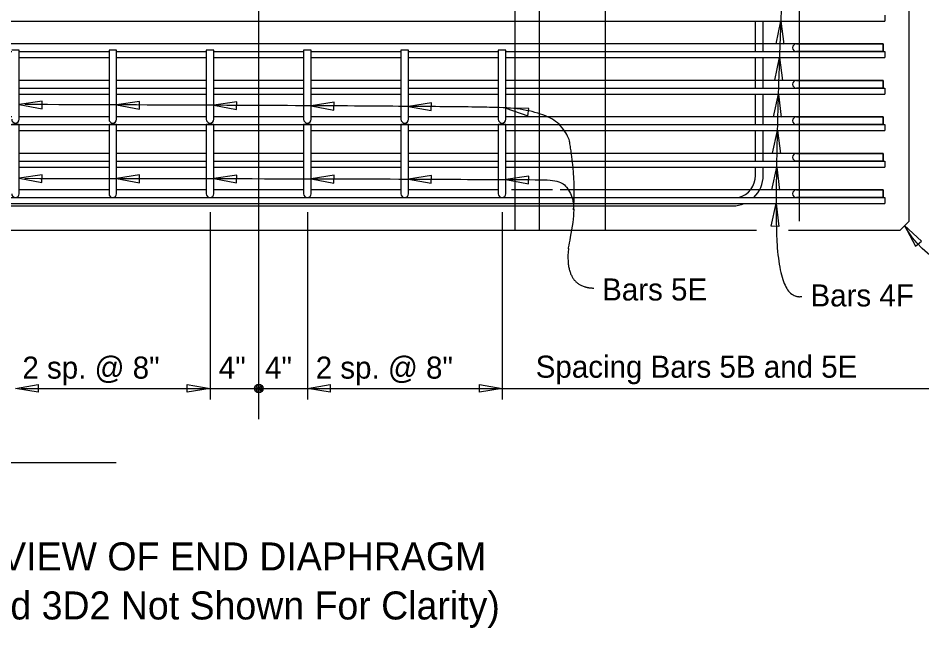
# Model space of a CAD drawing. Extents: x 120658.6 to 120712.1, y 120647.1 to 120669.9.
# Drawn here: x 120663.4 to 120669.6, y 120649.38 to 120653.56 of the extents above; entities that cross this region are included whole.
import ezdxf

# ---------------------------------------------------------------- set-up
doc = ezdxf.new("R2010")
doc.units = 0
for name, color, linetype in [('BeamConc', 7, 'Continuous'), ('BeamConc_h', 7, 'Continuous'), ('CL_Major', 7, 'Continuous'), ('Dimension', 7, 'Continuous'), ('Miscellaneous', 7, 'Continuous'), ('Rebar', 7, 'Continuous'), ('Rebar_h', 7, 'Continuous'), ('TextStructures', 7, 'Continuous')]:
    doc.layers.add(name, color=color, linetype=linetype)

msp = doc.modelspace()

# ---------------------------------------------------------------- linework, layer by layer
at = {"layer": 'BeamConc'}
for p, q in [((120669.5083, 120652.1656), (120669.5083, 120656.3833)), ((120669.4458, 120652.1031), (120669.5083, 120652.1656)), ((120660.7375, 120652.1031), (120668.4636, 120652.1031)), ((120668.6828, 120652.1031), (120669.4458, 120652.1031))]:
    msp.add_line(p, q, dxfattribs=at)
at = {"layer": 'BeamConc_h'}
for p, q in [((120667.425, 120656.3833), (120667.425, 120652.1031)), ((120668.7583, 120652.1656), (120668.7583, 120656.3833))]:
    msp.add_line(p, q, dxfattribs=at)
at = {"layer": 'CL_Major'}
msp.add_line((120665.0529, 120650.8078), (120665.0529, 120655.6993), dxfattribs=at)
at = {"layer": 'Dimension'}
for p, q in [((120664.7196, 120652.2276), (120664.7196, 120650.9437)), ((120665.3862, 120652.2276), (120665.3862, 120650.9437)), ((120666.7196, 120652.2276), (120666.7196, 120650.9437)), ((120663.425, 120651.0193), (120669.8858, 120651.0193)), ((120664.0762, 120650.5097), (120659.6749, 120650.5097))]:
    msp.add_line(p, q, dxfattribs=at)
for points in [[(120668.6295, 120653.5354), (120668.6493, 120653.3782), (120668.5964, 120653.3805)], [(120668.6206, 120653.2854), (120668.6403, 120653.1282), (120668.5874, 120653.1305)], [(120668.6128, 120653.0354), (120668.6325, 120652.8782), (120668.5797, 120652.8805)], [(120663.4122, 120652.9636), (120663.568, 120652.9349), (120663.5688, 120652.9878)], [(120664.0789, 120652.9614), (120664.2347, 120652.9326), (120664.2355, 120652.9855)], [(120664.7456, 120652.9586), (120664.9014, 120652.9299), (120664.9021, 120652.9828)], [(120665.4122, 120652.9553), (120665.568, 120652.9265), (120665.5688, 120652.9794)], [(120666.0789, 120652.9508), (120666.2347, 120652.922), (120666.2355, 120652.9749)], [(120666.7456, 120652.9381), (120666.8951, 120652.8857), (120666.904, 120652.9379)], [(120668.6063, 120652.7854), (120668.626, 120652.6282), (120668.5731, 120652.6305)], [(120668.6009, 120652.5354), (120668.6206, 120652.3782), (120668.5677, 120652.3805)], [(120663.4117, 120652.4584), (120663.5674, 120652.4297), (120663.5682, 120652.4826)], [(120664.0789, 120652.4575), (120664.2347, 120652.4287), (120664.2355, 120652.4816)], [(120664.7456, 120652.4564), (120664.9014, 120652.4276), (120664.9021, 120652.4805)], [(120665.4122, 120652.455), (120665.568, 120652.4262), (120665.5688, 120652.4791)], [(120666.0789, 120652.4531), (120666.2347, 120652.4243), (120666.2355, 120652.4772)], [(120666.7456, 120652.4495), (120666.9014, 120652.4207), (120666.9021, 120652.4736)], [(120668.5969, 120652.2854), (120668.6166, 120652.1282), (120668.5637, 120652.1305)], [(120669.4771, 120652.1344), (120669.5517, 120651.9946), (120669.5936, 120652.027)], [(120663.3862, 120651.0193), (120663.5419, 120651.0459), (120663.5419, 120650.9926)], [(120664.7195, 120651.0193), (120664.5633, 120650.9928), (120664.5633, 120651.0457)], [(120665.3862, 120651.0193), (120665.5424, 120651.0457), (120665.5424, 120650.9928)], [(120666.7195, 120651.0193), (120666.5639, 120650.9926), (120666.5639, 120651.0459)]]:
    msp.add_lwpolyline(points, close=True, dxfattribs=at)
for radius in [0.0299, 0.0196, 0.00888]:
    msp.add_circle((120665.0526, 120651.0188), radius, dxfattribs=at)
for points, degree in [([(120668.6397, 120653.7854), (120668.5921, 120652.6793), (120668.6046, 120651.6182), (120668.7732, 120651.6494)], 2), ([(120667.2092, 120652.2424), (120667.2258, 120652.4514), (120667.1449, 120652.9323), (120666.2289, 120652.9547), (120663.451, 120652.9637)], 2), ([(120663.4505, 120652.4585), (120666.8193, 120652.4545), (120667.2662, 120652.4382), (120667.1133, 120651.7115), (120667.3478, 120651.7067)], 2), ([(120670.6709, 120651.1441), (120670.3358, 120651.1038), (120670.1648, 120651.7005), (120669.6069, 120651.8964), (120669.4771, 120652.1344)], 3)]:
    msp.add_open_spline(points, degree=degree, dxfattribs=at)
at = {"layer": 'Miscellaneous'}
for p, q in [((120666.8065, 120654.1031), (120666.8065, 120652.1031)), ((120666.9732, 120654.1031), (120666.9732, 120652.1031))]:
    msp.add_line(p, q, dxfattribs=at)
at = {"layer": 'Rebar'}
for p, q in [((120669.3417, 120653.5771), (120669.3417, 120653.5354)), ((120660.8417, 120653.5354), (120669.3417, 120653.5354)), ((120668.4563, 120653.3271), (120668.4563, 120653.5354)), ((120668.5083, 120653.3271), (120668.5083, 120653.5354)), ((120668.7363, 120653.3792), (120669.3303, 120653.3792)), ((120669.3303, 120653.3792), (120669.3303, 120653.3271)), ((120663.4122, 120653.3371), (120663.3602, 120653.3371)), ((120663.4122, 120652.8631), (120663.4122, 120653.3371)), ((120663.4122, 120653.3271), (120664.0268, 120653.3271)), ((120664.0268, 120653.3371), (120664.0268, 120652.8631)), ((120664.0789, 120653.3371), (120664.0268, 120653.3371)), ((120664.0789, 120652.8631), (120664.0789, 120653.3371)), ((120664.0789, 120653.3271), (120664.6935, 120653.3271)), ((120664.6935, 120653.3371), (120664.6935, 120652.8631)), ((120664.7456, 120653.3371), (120664.6935, 120653.3371)), ((120664.7456, 120652.8631), (120664.7456, 120653.3371)), ((120664.7456, 120653.3271), (120665.3602, 120653.3271)), ((120665.3602, 120653.3371), (120665.3602, 120652.8631)), ((120665.4122, 120653.3371), (120665.3602, 120653.3371)), ((120665.4122, 120652.8631), (120665.4122, 120653.3371)), ((120665.4122, 120653.3271), (120666.0268, 120653.3271)), ((120666.0268, 120653.3371), (120666.0268, 120652.8631)), ((120666.0789, 120653.3371), (120666.0268, 120653.3371)), ((120666.0789, 120652.8631), (120666.0789, 120653.3371)), ((120666.0789, 120653.3271), (120666.6935, 120653.3271)), ((120666.6935, 120653.3371), (120666.6935, 120652.8631)), ((120666.7456, 120653.3371), (120666.6935, 120653.3371)), ((120666.7456, 120652.8631), (120666.7456, 120653.3371)), ((120666.7456, 120653.3271), (120669.3417, 120653.3271)), ((120669.3303, 120653.3271), (120668.7363, 120653.3271)), ((120669.3417, 120653.3271), (120669.3417, 120653.2854)), ((120663.4122, 120653.2854), (120664.0268, 120653.2854)), ((120664.0789, 120653.2854), (120664.6935, 120653.2854)), ((120664.7456, 120653.2854), (120665.3602, 120653.2854)), ((120665.4122, 120653.2854), (120666.0268, 120653.2854)), ((120666.0789, 120653.2854), (120666.6935, 120653.2854)), ((120666.7456, 120653.2854), (120669.3417, 120653.2854)), ((120668.4563, 120653.0771), (120668.4563, 120653.2854)), ((120668.5083, 120653.0771), (120668.5083, 120653.2854)), ((120668.7363, 120653.1292), (120669.3303, 120653.1292)), ((120669.3303, 120653.1292), (120669.3303, 120653.0771)), ((120663.4122, 120653.0771), (120664.0268, 120653.0771)), ((120664.0789, 120653.0771), (120664.6935, 120653.0771)), ((120664.7456, 120653.0771), (120665.3602, 120653.0771)), ((120665.4122, 120653.0771), (120666.0268, 120653.0771)), ((120666.0789, 120653.0771), (120666.6935, 120653.0771)), ((120666.7456, 120653.0771), (120669.3417, 120653.0771)), ((120669.3303, 120653.0771), (120668.7363, 120653.0771)), ((120669.3417, 120653.0771), (120669.3417, 120653.0354)), ((120663.4122, 120653.0354), (120664.0268, 120653.0354)), ((120664.0789, 120653.0354), (120664.6935, 120653.0354)), ((120664.7456, 120653.0354), (120665.3602, 120653.0354)), ((120665.4122, 120653.0354), (120666.0268, 120653.0354)), ((120666.0789, 120653.0354), (120666.6935, 120653.0354)), ((120666.7456, 120653.0354), (120669.3417, 120653.0354)), ((120668.4563, 120652.8271), (120668.4563, 120653.0354)), ((120668.5083, 120652.8271), (120668.5083, 120653.0354)), ((120660.8417, 120652.8271), (120669.3417, 120652.8271)), ((120663.4122, 120652.8271), (120663.3602, 120652.8271)), ((120663.4122, 120652.3532), (120663.4122, 120652.8271)), ((120664.0268, 120652.8271), (120664.0268, 120652.3532)), ((120664.0789, 120652.8271), (120664.0268, 120652.8271)), ((120664.0789, 120652.3532), (120664.0789, 120652.8271)), ((120664.6935, 120652.8271), (120664.6935, 120652.3532)), ((120664.7456, 120652.8271), (120664.6935, 120652.8271)), ((120664.7456, 120652.3532), (120664.7456, 120652.8271)), ((120665.3602, 120652.8271), (120665.3602, 120652.3532)), ((120665.4122, 120652.8271), (120665.3602, 120652.8271)), ((120665.4122, 120652.3532), (120665.4122, 120652.8271)), ((120666.0268, 120652.8271), (120666.0268, 120652.3532)), ((120666.0789, 120652.8271), (120666.0268, 120652.8271)), ((120666.0789, 120652.3532), (120666.0789, 120652.8271)), ((120666.6935, 120652.8271), (120666.6935, 120652.3532)), ((120666.7456, 120652.8271), (120666.6935, 120652.8271)), ((120666.7456, 120652.3532), (120666.7456, 120652.8271)), ((120668.7363, 120652.8792), (120669.3303, 120652.8792)), ((120669.3303, 120652.8271), (120668.7363, 120652.8271)), ((120669.3303, 120652.8792), (120669.3303, 120652.8271)), ((120669.3417, 120652.8271), (120669.3417, 120652.7854)), ((120663.4122, 120652.7854), (120664.0268, 120652.7854)), ((120664.0789, 120652.7854), (120664.6935, 120652.7854)), ((120664.7456, 120652.7854), (120665.3602, 120652.7854)), ((120665.4123, 120652.7854), (120666.0268, 120652.7854)), ((120666.0789, 120652.7854), (120666.6935, 120652.7854)), ((120666.7456, 120652.7854), (120669.3417, 120652.7854)), ((120668.4563, 120652.5771), (120668.4563, 120652.7854)), ((120668.5083, 120652.5771), (120668.5083, 120652.7854)), ((120663.4122, 120652.5771), (120664.0268, 120652.5771)), ((120664.0789, 120652.5771), (120664.6935, 120652.5771)), ((120664.7456, 120652.5771), (120665.3602, 120652.5771)), ((120665.4123, 120652.5771), (120666.0268, 120652.5771)), ((120666.0789, 120652.5771), (120666.6935, 120652.5771)), ((120666.7456, 120652.5771), (120669.3417, 120652.5771)), ((120668.7363, 120652.6292), (120669.3303, 120652.6292)), ((120669.3303, 120652.5771), (120668.7363, 120652.5771)), ((120669.3303, 120652.6292), (120669.3303, 120652.5771)), ((120669.3417, 120652.5771), (120669.3417, 120652.5354)), ((120663.4122, 120652.5354), (120664.0268, 120652.5354)), ((120664.0789, 120652.5354), (120664.6935, 120652.5354)), ((120664.7456, 120652.5354), (120665.3602, 120652.5354)), ((120665.4123, 120652.5354), (120666.0268, 120652.5354)), ((120666.0789, 120652.5354), (120666.6935, 120652.5354)), ((120666.7456, 120652.5354), (120669.3417, 120652.5354)), ((120668.4562, 120652.4781), (120668.4562, 120652.5354)), ((120668.5083, 120652.4781), (120668.5083, 120652.5354)), ((120663.0158, 120652.3271), (120669.3417, 120652.3271)), ((120668.7363, 120652.3792), (120669.3303, 120652.3792)), ((120669.3303, 120652.3271), (120668.7363, 120652.3271)), ((120669.3303, 120652.3792), (120669.3303, 120652.3271)), ((120669.3417, 120652.3271), (120669.3417, 120652.2854)), ((120661.8833, 120652.2698), (120668.3, 120652.2698)), ((120663.0158, 120652.2854), (120669.3417, 120652.2854))]:
    msp.add_line(p, q, dxfattribs=at)
for centre, radius, start, end in [((120668.7363, 120653.3532), 0.026, 90, 270), ((120668.7363, 120653.1032), 0.026, 90, 270), ((120663.3862, 120652.8631), 0.026, 179.99982, 359.99949), ((120664.0529, 120652.8631), 0.026, 179.99982, 359.99949), ((120664.7195, 120652.8631), 0.026, 179.99982, 359.99949), ((120665.3862, 120652.8631), 0.026, 179.99982, 359.99949), ((120666.0529, 120652.8631), 0.026, 179.99982, 359.99949), ((120666.7195, 120652.8631), 0.026, 179.99982, 359.99949), ((120668.7363, 120652.8532), 0.026, 90, 270), ((120668.7363, 120652.6032), 0.026, 90, 270), ((120668.3, 120652.4781), 0.1562, 284.80844, 360), ((120668.3, 120652.4781), 0.2083, 313.53337, 360), ((120663.3862, 120652.3532), 0.026, 179.99982, 359.99949), ((120664.0529, 120652.3532), 0.026, 179.99982, 359.99949), ((120664.7195, 120652.3532), 0.026, 179.99982, 359.99949), ((120665.3862, 120652.3532), 0.026, 179.99982, 359.99949), ((120666.0529, 120652.3532), 0.026, 179.99982, 359.99949), ((120666.7195, 120652.3532), 0.026, 179.99982, 359.99949), ((120668.7363, 120652.3532), 0.026, 90, 270), ((120668.3, 120652.4781), 0.2083, 270, 292.32843)]:
    msp.add_arc(centre, radius, start, end, dxfattribs=at)
at = {"layer": 'Rebar_h'}
for points in [[(120668.3586, 120653.3792), (120660.8531, 120653.3792), (120660.8531, 120653.3271), (120663.3602, 120653.3271)], [(120666.7844, 120653.3271), (120669.3303, 120653.3271), (120669.3303, 120653.3792), (120668.3586, 120653.3792)], [(120664.0268, 120653.1292), (120663.4122, 120653.1292)], [(120664.6935, 120653.1292), (120664.0789, 120653.1292)], [(120665.3602, 120653.1292), (120664.7456, 120653.1292)], [(120666.0268, 120653.1292), (120665.4122, 120653.1292)], [(120666.6935, 120653.1292), (120666.0789, 120653.1292)], [(120668.7363, 120653.0771), (120669.3303, 120653.0771), (120669.3303, 120653.1292), (120666.7456, 120653.1292)], [(120663.3602, 120652.8792), (120660.8531, 120652.8792), (120660.8531, 120652.8271), (120669.3303, 120652.8271), (120669.3303, 120652.8792), (120666.7456, 120652.8792)], [(120664.0268, 120652.8792), (120663.4122, 120652.8792)], [(120664.6935, 120652.8792), (120664.0789, 120652.8792)], [(120665.3602, 120652.8792), (120664.7456, 120652.8792)], [(120666.0268, 120652.8792), (120665.4122, 120652.8792)], [(120666.6935, 120652.8792), (120666.0789, 120652.8792)], [(120664.0268, 120652.6292), (120663.4122, 120652.6292)], [(120664.6935, 120652.6292), (120664.0789, 120652.6292)], [(120665.3602, 120652.6292), (120664.7456, 120652.6292)], [(120666.0268, 120652.6292), (120665.4122, 120652.6292)], [(120666.6935, 120652.6292), (120666.0789, 120652.6292)], [(120668.7363, 120652.5771), (120669.3303, 120652.5771), (120669.3303, 120652.6292), (120666.7456, 120652.6292)], [(120663.0158, 120652.3271), (120669.3303, 120652.3271), (120669.3303, 120652.3792), (120667.1177, 120652.3792)], [(120664.0268, 120652.3792), (120663.4122, 120652.3792)], [(120664.6935, 120652.3792), (120664.0789, 120652.3792)], [(120665.3602, 120652.3792), (120664.7456, 120652.3792)], [(120666.0268, 120652.3792), (120665.4123, 120652.3792)], [(120666.6935, 120652.3792), (120666.0789, 120652.3792)], [(120667.0656, 120652.3792), (120666.7844, 120652.3792)]]:
    msp.add_lwpolyline(points, dxfattribs=at)

# ---------------------------------------------------------------- texts
at = {"layer": 'Dimension'}
for s, p in [('TOP VIEW OF END DIAPHRAGM', (120662.6888, 120649.7723)), ('(Bars 3D1 And 3D2 Not Shown For Clarity)', (120661.8102, 120649.4363))]:
    msp.add_text(s, height=0.192, dxfattribs=at).set_placement(p)
at = {"layer": 'TextStructures'}
for s, p in [('Bars 5E', (120667.4051, 120651.6215)), ('Bars 4F', (120668.8325, 120651.5807)), ('2 sp. @ 8"', (120663.4333, 120651.0862)), ('4"', (120664.7791, 120651.0862)), ('4"', (120665.096, 120651.0862)), ('2 sp. @ 8"', (120665.4428, 120651.0862)), ('Spacing Bars 5B and 5E', (120666.9502, 120651.0924))]:
    msp.add_text(s, height=0.1512, dxfattribs=at).set_placement(p)

doc.saveas('drawing.dxf')
